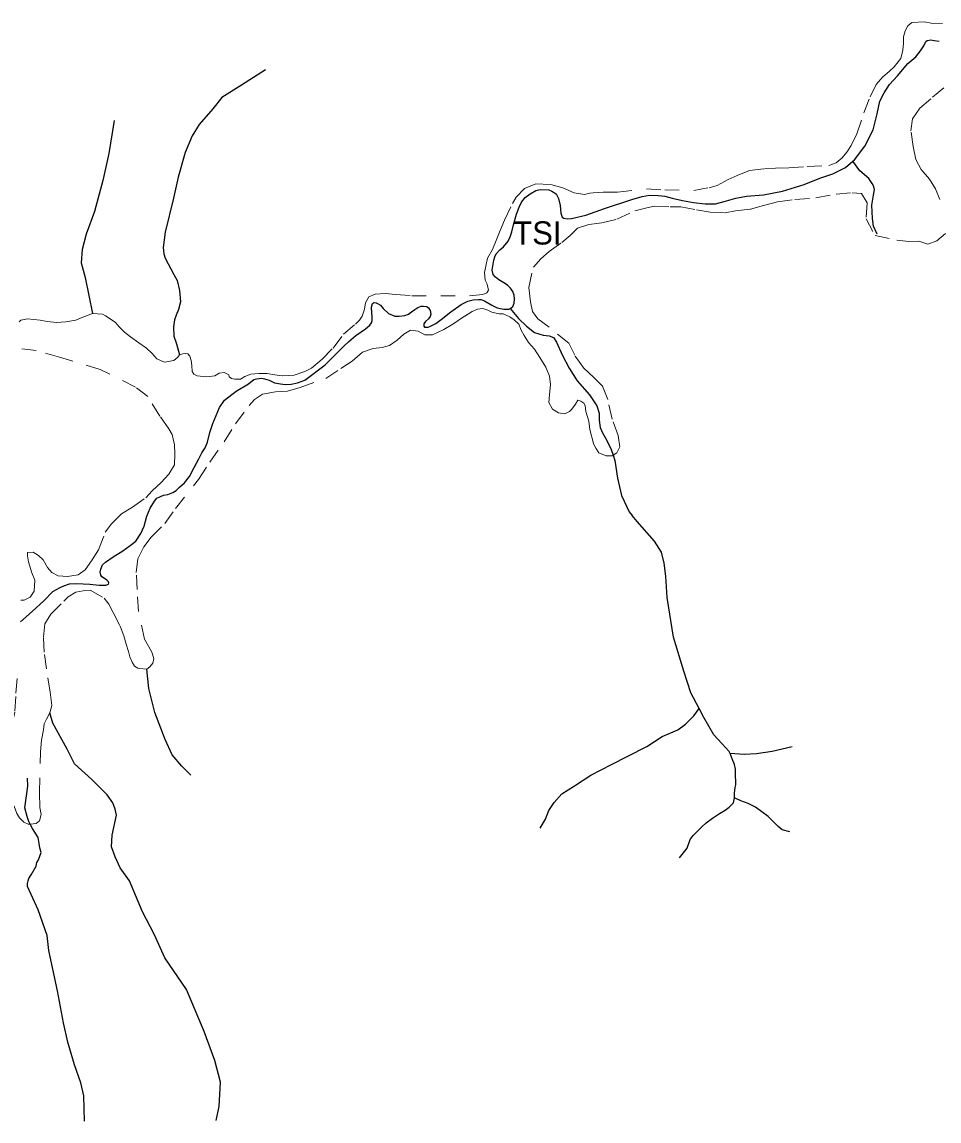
# Model space of a CAD drawing. Extents: x 391.8 to 446, y 8452 to 8507.5.
# Drawn here: x 413.89 to 420.22, y 8470.84 to 8478.42 of the extents above; entities that cross this region are included whole.
import ezdxf
from ezdxf.enums import TextEntityAlignment as Align

# ---------------------------------------------------------------- set-up
doc = ezdxf.new("R2010")
doc.units = 0
doc.header["$LTSCALE"] = 0.064
doc.linetypes.add('LONG_DASHED', pattern=[7.5, 6, -1.5])
doc.linetypes.add('SHORT_DASHED', pattern=[2.7, 1.5, -1.2])
for name, color, linetype, lineweight in [('21', 7, 'SHORT_DASHED', 13), ('7', 7, 'Continuous', 25), ('9', 7, 'LONG_DASHED', 25)]:
    doc.layers.add(name, color=color, linetype=linetype, lineweight=lineweight)
doc.layers.add('61', color=7, linetype='Continuous')

msp = doc.modelspace()

# ---------------------------------------------------------------- linework, layer by layer
at = {"layer": '21'}
for points in [[(415.3254, 8475.9726), (415.3407, 8475.9611), (415.3637, 8475.9573), (415.4021, 8475.9573), (415.4327, 8475.9765), (415.4749, 8475.9918), (415.5285, 8475.9956), (415.586, 8475.9956), (415.6397, 8475.9879), (415.6895, 8475.9803), (415.7739, 8475.9841), (415.8467, 8476.0109), (415.8927, 8476.0339), (415.9655, 8476.0951), (416.0422, 8476.1717), (416.1128, 8476.269), (416.1971, 8476.3379), (416.224, 8476.3647), (416.2431, 8476.3915), (416.2585, 8476.4413), (416.2661, 8476.4834), (416.2891, 8476.5255), (416.3313, 8476.5447), (416.4041, 8476.5485), (416.4731, 8476.5408), (416.5843, 8476.5332), (416.983, 8476.5332), (417.075, 8476.5408), (417.1018, 8476.5523), (417.1133, 8476.5714), (417.1056, 8476.6136), (417.0903, 8476.6404), (417.0865, 8476.694), (417.1064, 8476.7913), (417.1409, 8476.8525), (417.1677, 8476.9138), (417.1945, 8476.9827), (417.2252, 8477.0554), (417.2789, 8477.1703), (417.3057, 8477.2124), (417.3632, 8477.2736), (417.4399, 8477.3042), (417.5434, 8477.3004), (417.6277, 8477.2774), (417.7044, 8477.243), (417.7772, 8477.2315), (417.8133, 8477.2401), (417.8363, 8477.2439), (417.9053, 8477.2478), (418.0049, 8477.2478), (418.2043, 8477.2707), (418.3308, 8477.2631), (418.5301, 8477.2592), (418.6374, 8477.2784), (418.6911, 8477.2937), (418.7677, 8477.3358), (418.8291, 8477.3626), (418.9155, 8477.3973), (419.019, 8477.4088), (419.0957, 8477.4126), (419.1877, 8477.4165), (419.3142, 8477.4241), (419.4636, 8477.4318), (419.5135, 8477.4509), (419.5556, 8477.4854), (419.5863, 8477.5237), (419.617, 8477.5696), (419.6553, 8477.65), (419.7051, 8477.7955), (419.7473, 8477.9065), (419.7895, 8477.9907), (419.8366, 8478.0429), (419.8788, 8478.0812), (419.9133, 8478.1118), (419.9593, 8478.1692), (419.9746, 8478.2266), (419.9784, 8478.2764), (419.9784, 8478.3185), (419.9899, 8478.3606), (420.0091, 8478.3951), (420.0359, 8478.4181), (420.1203, 8478.4219), (420.1701, 8478.4142), (420.2468, 8478.4104)], [(420.2293, 8477.1976), (420.1982, 8477.2701), (420.1567, 8477.3374), (420.0997, 8477.4047), (420.0634, 8477.472), (420.0443, 8477.5622), (420.0288, 8477.6709), (420.0391, 8477.7537), (420.091, 8477.8262), (420.1791, 8477.9039), (420.3502, 8478.0436)], [(417.9738, 8475.4324), (417.9991, 8475.4493), (418.0199, 8475.4907), (418.0095, 8475.5683), (417.968, 8475.6822), (417.9369, 8475.8168), (417.9006, 8475.91), (417.8384, 8475.9721), (417.771, 8476.0343), (417.7088, 8476.1223), (417.6674, 8476.2051), (417.5324, 8476.3161), (417.4546, 8476.373), (417.4183, 8476.4248), (417.4028, 8476.4921), (417.3924, 8476.5904), (417.4235, 8476.7302), (417.4754, 8476.7872), (417.5324, 8476.8389), (417.6205, 8476.9011), (417.6775, 8476.9477), (417.7294, 8476.9994), (417.8071, 8477.0253), (417.8953, 8477.0357), (417.9989, 8477.0615), (418.1233, 8477.1185), (418.2076, 8477.1407), (418.2595, 8477.151), (418.3683, 8477.1459), (418.4409, 8477.1459), (418.5498, 8477.1252), (418.6431, 8477.1096), (418.7467, 8477.1045), (418.8193, 8477.12), (418.923, 8477.1303), (419.0111, 8477.1562), (419.1096, 8477.1821), (419.2288, 8477.1976), (419.374, 8477.208), (419.5139, 8477.2339), (419.6228, 8477.2442), (419.6887, 8477.2385), (419.7285, 8477.1738), (419.7206, 8477.0642), (419.7816, 8476.9497), (419.933, 8476.9174), (420.0153, 8476.9074), (420.0842, 8476.9095), (420.1464, 8476.8887), (420.2086, 8476.9129), (420.2675, 8476.9622)], [(413.8745, 8476.3534), (413.8867, 8476.3651), (413.9318, 8476.3748), (414.0188, 8476.3651), (414.0671, 8476.3555), (414.1316, 8476.3491), (414.196, 8476.3523), (414.2669, 8476.3651), (414.3023, 8476.3812), (414.3808, 8476.4104)], [(414.3808, 8476.4104), (414.4505, 8476.407), (414.4699, 8476.3941), (414.4956, 8476.378), (414.5407, 8476.3491), (414.5633, 8476.3201), (414.6019, 8476.2815), (414.6438, 8476.2493), (414.7018, 8476.2075), (414.7534, 8476.1721), (414.792, 8476.1335), (414.8242, 8476.0981), (414.85, 8476.0852), (414.879, 8476.0756), (414.9429, 8476.0873), (414.9691, 8476.1085), (414.9821, 8476.1249)], [(414.7554, 8473.9559), (414.7767, 8473.9737), (414.7981, 8473.9981), (414.8042, 8474.0301), (414.7905, 8474.0728), (414.7676, 8474.1155), (414.7401, 8474.1627), (414.6988, 8474.3551), (414.6884, 8474.5052), (414.6832, 8474.6243), (414.6936, 8474.7175), (414.7351, 8474.8003), (414.7869, 8474.8676), (414.8802, 8474.9608), (414.9528, 8475.0643), (415.1135, 8475.2662), (415.1912, 8475.3853), (415.2897, 8475.5251), (415.3675, 8475.6493), (415.4621, 8475.7767), (415.4984, 8475.8181), (415.5554, 8475.8544), (415.6435, 8475.8699), (415.7265, 8475.8751), (415.8146, 8475.901), (415.9908, 8475.9631), (416.0945, 8476.0304), (416.1723, 8476.0822), (416.2448, 8476.1443), (416.3174, 8476.1702), (416.3796, 8476.1753), (416.4314, 8476.1909), (416.4833, 8476.2271), (416.5299, 8476.2685), (416.5766, 8476.2944), (416.6284, 8476.2892), (416.6751, 8476.2633), (416.7269, 8476.2633), (416.8047, 8476.2996), (416.8669, 8476.3358), (416.9498, 8476.3928), (417.0017, 8476.4238), (417.038, 8476.4394)], [(417.038, 8476.4394), (417.0742, 8476.4445), (417.1105, 8476.4342), (417.1364, 8476.4187), (417.1883, 8476.4083), (417.2142, 8476.4083), (417.2609, 8476.3876)], [(417.2609, 8476.3876), (417.292, 8476.3669), (417.3231, 8476.3358), (417.3386, 8476.2944), (417.3594, 8476.2582), (417.3905, 8476.2116), (417.4319, 8476.165), (417.4682, 8476.108), (417.5097, 8476.0407), (417.5356, 8475.9786), (417.5408, 8475.9217), (417.5356, 8475.8492), (417.5304, 8475.7974), (417.5563, 8475.7508), (417.5978, 8475.7249), (417.6415, 8475.7185), (417.6726, 8475.734), (417.6881, 8475.7495), (417.714, 8475.7858), (417.7296, 8475.8117), (417.7503, 8475.8065), (417.771, 8475.7909), (417.7814, 8475.7754), (417.7866, 8475.734), (417.8073, 8475.6667), (417.8125, 8475.6097), (417.8384, 8475.5114), (417.854, 8475.4803), (417.8747, 8475.4493), (417.9266, 8475.4285), (417.968, 8475.4285), (417.9738, 8475.4324)], [(413.8864, 8474.4337), (413.9094, 8474.4337), (413.9515, 8474.4528), (413.9784, 8474.4949), (413.9822, 8474.5715), (413.963, 8474.6213), (413.94, 8474.6978), (413.9326, 8474.7376), (413.9326, 8474.7606), (413.9709, 8474.7644), (414.0092, 8474.7415), (414.0399, 8474.7108), (414.0706, 8474.6572), (414.1012, 8474.6228), (414.1434, 8474.5998), (414.2086, 8474.596), (414.2814, 8474.6075), (414.3312, 8474.6419), (414.3734, 8474.7032), (414.4232, 8474.7797), (414.4692, 8474.9022), (414.5114, 8474.9597), (414.5804, 8475.0286), (414.6571, 8475.0745), (414.7491, 8475.1396), (414.7926, 8475.1864), (414.8539, 8475.2438), (414.9076, 8475.3012), (414.9459, 8475.3663), (414.9498, 8475.4429), (414.9459, 8475.5041), (414.9306, 8475.5768), (414.9076, 8475.6151), (414.8463, 8475.7032), (414.763, 8475.8375), (414.6786, 8475.9028), (414.4342, 8476.0249), (414.2462, 8476.0812), (414.1522, 8476.1093), (413.9925, 8476.1563), (413.8803, 8476.1689)], [(414.9821, 8476.1249), (415.0035, 8476.1331), (415.0249, 8476.1347), (415.038, 8476.1331), (415.0527, 8476.1151), (415.0609, 8476.0873), (415.0659, 8476.0512), (415.0686, 8476.0109), (415.0801, 8475.9918), (415.1031, 8475.9803)], [(415.1031, 8475.9803), (415.1682, 8475.9726), (415.2257, 8475.9803), (415.2564, 8475.9994), (415.2909, 8476.0033), (415.3216, 8475.9879), (415.3254, 8475.9726)], [(414.0874, 8473.6547), (414.0998, 8473.7054), (414.0894, 8473.7986), (414.0635, 8473.9591), (414.0479, 8474.073), (414.0427, 8474.1765), (414.0531, 8474.2697), (414.0946, 8474.337), (414.1827, 8474.425), (414.2138, 8474.4561), (414.2656, 8474.4871), (414.3175, 8474.4975), (414.3641, 8474.5027), (414.4626, 8474.4457), (414.4937, 8474.4043), (414.5248, 8474.3473), (414.5715, 8474.2542), (414.5974, 8474.1869), (414.613, 8474.1299), (414.6285, 8474.0781), (414.6389, 8474.0419), (414.6544, 8474.0057), (414.6699, 8473.9768), (414.6928, 8473.963), (414.7081, 8473.9615), (414.7554, 8473.9559)], [(413.8613, 8473.8918), (413.8509, 8473.7675), (413.8457, 8473.6588), (413.825, 8473.5656), (413.8095, 8473.4724), (413.7939, 8473.3792), (413.7887, 8473.2861), (413.7791, 8473.1955), (413.7843, 8473.1385), (413.804, 8473.0961), (413.818, 8473.0523), (413.8399, 8473.0105), (413.8578, 8472.9607), (413.8778, 8472.9309), (413.9077, 8472.901), (413.9376, 8472.8871), (413.9506, 8472.888)], [(413.9506, 8472.888), (413.9914, 8472.891), (414.0153, 8472.911), (414.0273, 8472.9528), (414.0173, 8473.0026), (414.0153, 8473.1061), (414.0216, 8473.3859), (414.0295, 8473.4656), (414.0435, 8473.5373), (414.0475, 8473.5791), (414.0634, 8473.6109), (414.0874, 8473.6547)]]:
    msp.add_lwpolyline(points, dxfattribs=at)
at = {"layer": '7'}
for points in [[(419.6289, 8477.4615), (419.6403, 8477.4712), (419.7109, 8477.5644), (419.7678, 8477.6781), (419.7955, 8477.7883), (419.8137, 8477.8747), (419.8456, 8477.9338), (419.882, 8477.9906), (419.9366, 8478.0497), (420.0072, 8478.1361), (420.064, 8478.1815), (420.0965, 8478.2235), (420.1192, 8478.2576), (420.1283, 8478.2781), (420.1329, 8478.2872), (420.142, 8478.294), (420.167, 8478.2985), (420.1898, 8478.294), (420.2239, 8478.2894)], [(417.2635, 8476.4445), (417.2705, 8476.4485), (417.2819, 8476.4599), (417.291, 8476.4826), (417.2933, 8476.5122), (417.291, 8476.5372), (417.2819, 8476.5622), (417.266, 8476.5849), (417.2455, 8476.6054), (417.2204, 8476.6213), (417.1863, 8476.6417), (417.1613, 8476.6622), (417.1453, 8476.6804), (417.1385, 8476.7099), (417.1453, 8476.7508), (417.1499, 8476.7781), (417.1567, 8476.8008), (417.1681, 8476.8213), (417.1931, 8476.8508), (417.2182, 8476.8713), (417.25, 8476.9093), (417.2637, 8476.9388), (417.2751, 8476.9729), (417.2864, 8477.0229), (417.3069, 8477.0957), (417.3251, 8477.1434), (417.3411, 8477.1798), (417.3661, 8477.2116), (417.4025, 8477.2366), (417.4412, 8477.2593), (417.4708, 8477.2661), (417.5299, 8477.2639), (417.5504, 8477.2548), (417.58, 8477.2366), (417.5982, 8477.2048), (417.6096, 8477.1548), (417.6142, 8477.1025), (417.6233, 8477.0752), (417.6346, 8477.0684), (417.6597, 8477.0638), (417.687, 8477.0661), (417.7848, 8477.0888), (417.9145, 8477.1343), (418.1026, 8477.1981), (418.1754, 8477.2186), (418.2255, 8477.2277), (418.2846, 8477.2254), (418.3302, 8477.2209), (418.3825, 8477.2072), (418.453, 8477.1891), (418.5281, 8477.1754), (418.6101, 8477.1663), (418.6806, 8477.1663), (418.7398, 8477.1822), (418.8217, 8477.2072), (418.8945, 8477.2209), (419.0129, 8477.23), (419.142, 8477.2553), (419.2922, 8477.3008), (419.4014, 8477.344), (419.4902, 8477.3735), (419.5789, 8477.419), (419.6289, 8477.4615)], [(419.7956, 8476.958), (419.7714, 8477.0123), (419.7653, 8477.0667), (419.7593, 8477.1573), (419.7714, 8477.2268), (419.7774, 8477.2661), (419.7744, 8477.2872), (419.7623, 8477.3084), (419.7381, 8477.3416), (419.6776, 8477.396), (419.6289, 8477.4615)], [(413.8843, 8474.2837), (413.9651, 8474.3545), (414.0458, 8474.4285), (414.1084, 8474.4926), (414.1578, 8474.519), (414.1825, 8474.5321), (414.222, 8474.5453), (414.2715, 8474.5469), (414.3621, 8474.5436), (414.4263, 8474.5354), (414.4724, 8474.5371), (414.4922, 8474.542), (414.4939, 8474.5519), (414.4922, 8474.5585), (414.4807, 8474.57), (414.4642, 8474.5815), (414.4461, 8474.5947), (414.4378, 8474.6062), (414.4346, 8474.6259), (414.4378, 8474.6473), (414.4494, 8474.6753), (414.4708, 8474.695), (414.5229, 8474.7322), (414.5905, 8474.7733), (414.6415, 8474.8095), (414.6794, 8474.8408), (414.714, 8474.8918), (414.7387, 8474.9428), (414.7568, 8475.0119), (414.7782, 8475.0685), (414.8079, 8475.1146), (414.8244, 8475.136), (414.8458, 8475.1458), (414.8721, 8475.1573), (414.9018, 8475.1606), (414.9364, 8475.1754), (414.9594, 8475.1902), (414.9825, 8475.2133), (415.0155, 8475.2413), (415.05, 8475.2857), (415.0819, 8475.3478), (415.1149, 8475.4087), (415.1346, 8475.4482), (415.1593, 8475.4827), (415.1742, 8475.5239), (415.1906, 8475.5897), (415.2104, 8475.6506), (415.2335, 8475.7065), (415.2565, 8475.7624), (415.2928, 8475.8134), (415.3723, 8475.8737), (415.4579, 8475.9247), (415.4942, 8475.9543), (415.5139, 8475.9592), (415.5502, 8475.9642), (415.5683, 8475.9609), (415.5996, 8475.951), (415.6375, 8475.9329), (415.6787, 8475.9247), (415.71, 8475.9214), (415.7512, 8475.923), (415.7956, 8475.9329), (415.8467, 8475.951), (415.9867, 8476.0563), (416.1129, 8476.1838), (416.1508, 8476.2167), (416.1986, 8476.2578), (416.2645, 8476.3039), (416.2958, 8476.3302), (416.3073, 8476.3466), (416.3106, 8476.3631), (416.3106, 8476.3894), (416.3089, 8476.4157), (416.3056, 8476.4552), (416.3139, 8476.4799)], [(416.3139, 8476.4799), (416.3205, 8476.4848), (416.3254, 8476.4865), (416.3386, 8476.4848), (416.3485, 8476.4799), (416.3682, 8476.4684), (416.3864, 8476.4453)], [(416.3864, 8476.4453), (416.4243, 8476.4108), (416.4687, 8476.3911), (416.4967, 8476.3911), (416.5363, 8476.396), (416.5626, 8476.4059), (416.5824, 8476.4223), (416.6055, 8476.4371), (416.6269, 8476.4519), (416.6483, 8476.4601), (416.6664, 8476.4618), (416.6878, 8476.4585), (416.701, 8476.4486), (416.7125, 8476.4322), (416.7158, 8476.4059), (416.7109, 8476.3894), (416.701, 8476.373), (416.6796, 8476.3549), (416.6681, 8476.3384), (416.6681, 8476.322), (416.673, 8476.317), (416.6812, 8476.317), (416.6977, 8476.3154), (416.7092, 8476.3203), (416.7241, 8476.3269), (416.7504, 8476.3417), (416.7883, 8476.368), (416.8551, 8476.4227), (416.926, 8476.4737), (416.9705, 8476.4951), (417.0084, 8476.5049), (417.0446, 8476.5082), (417.0644, 8476.5066), (417.0858, 8476.4983), (417.1368, 8476.4687), (417.1747, 8476.449), (417.2209, 8476.4408), (417.2546, 8476.4394), (417.2635, 8476.4445)], [(417.2635, 8476.4445), (417.3211, 8476.3755), (417.3767, 8476.3239), (417.4323, 8476.2803), (417.4919, 8476.2605), (417.5316, 8476.2565), (417.5634, 8476.2446), (417.5833, 8476.2129), (417.623, 8476.1256), (417.6707, 8476.0343), (417.7263, 8475.9471), (417.8101, 8475.8493), (417.8618, 8475.774), (417.8777, 8475.7224), (417.8777, 8475.6748), (417.8856, 8475.6232), (417.9015, 8475.5875), (417.9293, 8475.5399), (417.9611, 8475.4725), (417.9738, 8475.4324)], [(417.9738, 8475.4324), (417.9849, 8475.3971), (418.0048, 8475.2741), (418.0326, 8475.1551), (418.0846, 8475.0418), (418.1058, 8475.0161)]]:
    msp.add_lwpolyline(points, dxfattribs=at)
at = {"layer": '9'}
for points in [[(415.5742, 8478.0925), (415.4102, 8477.9857), (415.2747, 8477.9003), (415.2105, 8477.8219), (415.1179, 8477.7151), (415.0679, 8477.6368), (415.0207, 8477.5222), (414.9714, 8477.3501), (414.9397, 8477.206), (414.8835, 8476.9706), (414.8694, 8476.8652), (414.8729, 8476.8231), (414.8835, 8476.7915), (414.9433, 8476.679), (414.9645, 8476.6389), (414.982, 8476.5687), (414.9891, 8476.4914), (414.975, 8476.4387), (414.9574, 8476.4), (414.9469, 8476.3673), (414.9399, 8476.3181), (414.9434, 8476.2549), (414.961, 8476.2022), (414.9821, 8476.1249)], [(414.5305, 8477.742), (414.4949, 8477.5141), (414.4521, 8477.329), (414.395, 8477.1153), (414.338, 8476.9587), (414.3095, 8476.8519), (414.3023, 8476.7593), (414.3309, 8476.6596), (414.3808, 8476.4104)], [(418.5671, 8473.686), (418.5098, 8473.793), (418.4621, 8473.9437), (418.3905, 8474.177), (418.3468, 8474.4507), (418.3388, 8474.5975), (418.3269, 8474.6887), (418.307, 8474.7641), (418.2594, 8474.8395), (418.1402, 8474.9744), (418.1058, 8475.0161)], [(415.0588, 8473.226), (414.9981, 8473.2866), (414.9319, 8473.3665), (414.8823, 8473.4711), (414.8106, 8473.6584), (414.7692, 8473.8237), (414.7554, 8473.9559)], [(417.4715, 8472.8602), (417.5076, 8472.9225), (417.5306, 8472.9815), (417.5667, 8473.0372), (417.6192, 8473.0963), (417.7078, 8473.152), (417.8194, 8473.2241), (417.9638, 8473.2995), (418.0754, 8473.3552), (418.2067, 8473.4241), (418.3118, 8473.4929), (418.4201, 8473.5388), (418.4726, 8473.5781), (418.5317, 8473.6338), (418.5671, 8473.686)], [(418.7813, 8473.3744), (418.7759, 8473.3883), (418.7243, 8473.4439), (418.6687, 8473.5034), (418.6012, 8473.6224), (418.5671, 8473.686)], [(415.2354, 8470.8436), (415.2554, 8470.9383), (415.2653, 8471.1078), (415.2254, 8471.2573), (415.1506, 8471.4567), (415.0308, 8471.7458), (414.881, 8471.9652), (414.806, 8472.1277), (414.7262, 8472.2822), (414.6363, 8472.4965), (414.5715, 8472.5863), (414.5365, 8472.661), (414.5116, 8472.7308), (414.5166, 8472.8106), (414.5465, 8472.9501), (414.5365, 8472.99), (414.5216, 8473.0349), (414.4816, 8473.0897), (414.3768, 8473.1944), (414.257, 8473.3041), (414.2072, 8473.4054), (414.1073, 8473.5849), (414.0874, 8473.6547)], [(419.2092, 8473.4209), (419.0713, 8473.3882), (418.963, 8473.3718), (418.8776, 8473.3685), (418.7813, 8473.3744)], [(418.8108, 8473.0687), (418.8115, 8473.0769), (418.8111, 8473.1004), (418.8167, 8473.1406), (418.8199, 8473.1586), (418.8202, 8473.1846), (418.8191, 8473.2178), (418.818, 8473.2677), (418.8116, 8473.2996), (418.7958, 8473.3368), (418.7813, 8473.3744)], [(413.9506, 8472.888), (413.9422, 8472.9048), (413.9309, 8472.9406), (413.9142, 8473.0003), (413.9342, 8473.1501), (413.9317, 8473.2051)], [(418.4327, 8472.654), (418.486, 8472.7219), (418.5058, 8472.7814), (418.5257, 8472.8091), (418.5535, 8472.8369), (418.5853, 8472.8686), (418.6171, 8472.8964), (418.6608, 8472.9281), (418.7084, 8472.9599), (418.7481, 8472.9837), (418.7759, 8473.0035), (418.8038, 8473.0353), (418.8108, 8473.0687)], [(419.1927, 8472.8342), (419.1402, 8472.8473), (419.114, 8472.8702), (419.045, 8472.9391), (418.9564, 8473.0046), (418.9072, 8473.0308), (418.8547, 8473.0472), (418.8108, 8473.0687)], [(414.3262, 8470.839), (414.3213, 8471.0135), (414.3013, 8471.1032), (414.2564, 8471.2278), (414.2115, 8471.3823), (414.1815, 8471.5169), (414.1391, 8471.7373), (414.0792, 8472.0165), (414.068, 8472.1185), (414.0067, 8472.2963), (413.9567, 8472.4026), (413.9317, 8472.4575), (413.9317, 8472.4774), (413.9367, 8472.4973), (413.9417, 8472.5123), (413.9567, 8472.5372), (413.9916, 8472.597), (413.9966, 8472.6219), (414.009, 8472.6417), (414.026, 8472.6914), (414.0186, 8472.7235), (414.0136, 8472.7534), (414.0061, 8472.7962), (413.9666, 8472.8562), (413.9506, 8472.888)]]:
    msp.add_lwpolyline(points, dxfattribs=at)

# ---------------------------------------------------------------- texts
at = {"layer": '61'}
msp.add_text('TSI', height=0.16, dxfattribs=at).set_placement((417.4514, 8476.8864), align=Align.CENTER)

doc.saveas('drawing.dxf')
